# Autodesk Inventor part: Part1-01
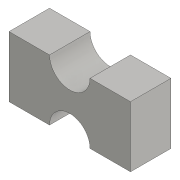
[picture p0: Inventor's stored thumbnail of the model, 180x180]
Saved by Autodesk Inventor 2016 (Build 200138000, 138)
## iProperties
Created: 2015-05
Part Number: Part1-01
Material: Generic
Document SubType Name: Modeling
Designer: Sandeep
Density: 1 g/cm^3
Appearance: Default
Author: Sandeep
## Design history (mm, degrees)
sketch "Sketch1"
  geometry: L1 (-30, -15)-(-10, -15); L2 (10, -15)-(30, -15); L3 (30, -15)-(30, 15); L4 (30, 15)-(10, 15); L5 (-10, 15)-(-30, 15); L6 (-30, 15)-(-30, -15); L7 (0, 32.136)-(0, -32.65); L8 (0, 0)-(-56.58, 0); A1 r 10 centre (0, -15) between (10, -15) and (-10, -15); A2 r 10 centre (0, 15) between (-10, 15) and (10, 15)
  constraints: 16 end point, 9 point on line, 4 point on circle, 3 perpendicular, 2 centre point, 2 horizontal, 1 equal radius, 1 vertical, 2 other
  dimensions: "d3" = 60 distance between parallel lines of L3 L6 (= LEN); "d4" = 30 distance between parallel lines of L1 L5 (= WID); "d5" = 10 radius of A2 (= RAD)
extrude "Extrusion1" new body sketch "Sketch1" distance "d6" = 20 (= EXT); taper "d7" = 0 deg
fillet "Fillet1" dims "d8" = 6 (= FILLET)
body "Solid1"
other parameters: "LEN" = 60 [user parameter; used in 5 equation terms], "WID" = 30 (= 0.5 x LEN) [user parameter; used in 1 equation term], "RAD" = 10 (= 0.166667 x LEN) [user parameter; used in 1 equation term], "EXT" = 20 (= 0.333333 x LEN) [user parameter; used in 1 equation term], "FILLET" = 6 (= 0.1 x LEN) [user parameter; used in 1 equation term]
